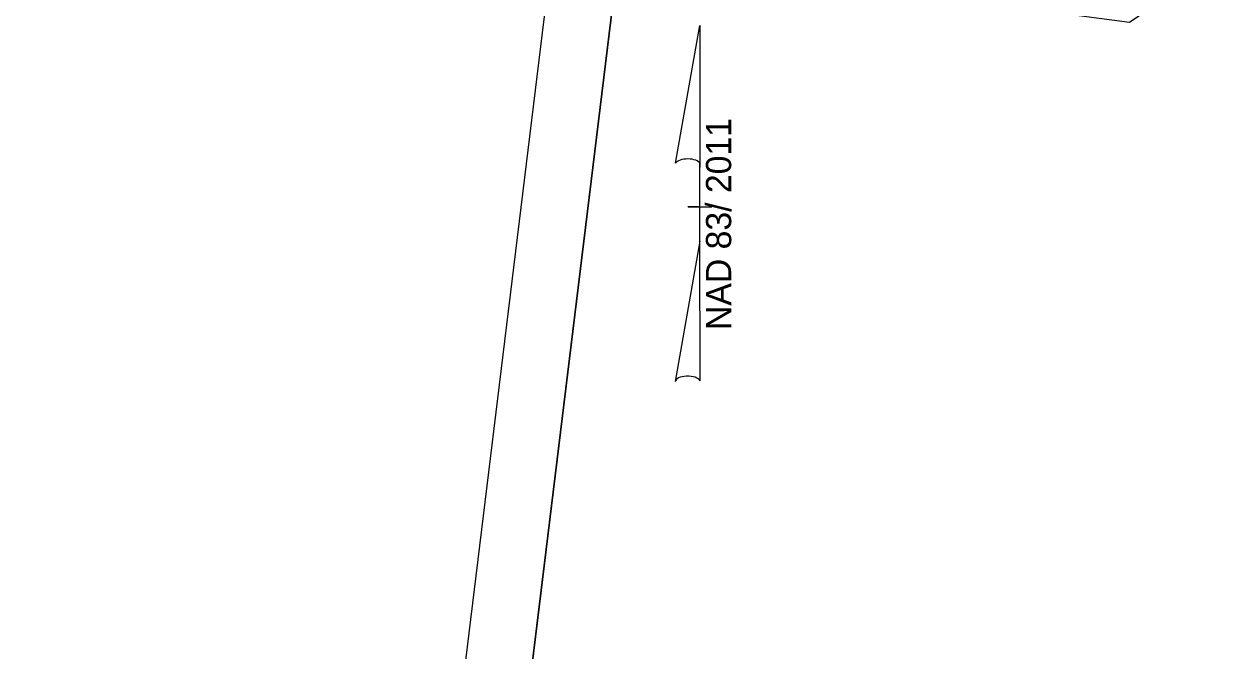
# Model space of a CAD drawing. Extents: x 480792 to 482083, y 490046 to 491850.
# Drawn here: x 480791.8 to 481196.3, y 491399.2 to 491610.4 of the extents above; entities that cross this region are included whole.
import ezdxf

# ---------------------------------------------------------------- set-up
doc = ezdxf.new("R2010")
doc.units = 0
for name, color, linetype in [('Prop North Arrow NAD83 for Plan Sheets CELL', 7, 'Continuous'), ('Sheet Clip Boundary CELL', 7, 'Continuous'), ('Sheet Plan CELL', 7, 'Continuous'), ('Sheet Plot Border Outside CELL', 7, 'Continuous')]:
    doc.layers.add(name, color=color, linetype=linetype)

msp = doc.modelspace()

# ---------------------------------------------------------------- linework, layer by layer
at = {"layer": 'Prop North Arrow NAD83 for Plan Sheets CELL'}
for p, q in [((481011.23, 491563.5), (481019.43, 491609.85)), ((481019.48, 491609.85), (481019.43, 491609.85)), ((481019.48, 491609.85), (481019.43, 491609.85)), ((481019.48, 491609.85), (481019.48, 491562.05)), ((481019.48, 491537.25), (481019.48, 491563.45)), ((481019.48, 491562.05), (481019.48, 491563.4)), ((481015.48, 491548.85), (481015.43, 491548.85)), ((481019.03, 491548.85), (481015.48, 491548.85)), ((481015.53, 491548.85), (481023.53, 491548.85)), ((481019.48, 491537.25), (481011.13, 491490)), ((481019.53, 491490.2), (481019.48, 491537.25))]:
    msp.add_line(p, q, dxfattribs=at)
for centre, start_param, end_param in [((481015.37, 491563), 0.216388, 2.908219), ((481015.37, 491489.83), 0.201328, 3.141593)]:
    msp.add_ellipse(centre, major_axis=(4.23, -0.03), ratio=0.461098, start_param=start_param, end_param=end_param, dxfattribs=at)
at = {"layer": 'Sheet Clip Boundary CELL'}
msp.add_lwpolyline([(480960.89, 490427.66), (481123.7, 490407.77), (481546.78, 490356.1), (481674.49, 490340.53), (481662.51, 490242.06), (481694.92, 490236.5), (481876.58, 490214.31), (482038.38, 491533.84), (481958.33, 491543.66), (481978.88, 491711.23), (481782.84, 491735.27), (481563.21, 491713.66), (481210.33, 491642.39), (481164.2, 491610.96), (481026.3, 491629.16), (480991.92, 491631.99), (480846.54, 490441.62)], close=True, dxfattribs=at)
at = {"layer": 'Sheet Plan CELL'}
for points in [[(481016.19, 491830.58), (480834.33, 490341.61), (481876.58, 490214.31), (482058.44, 491703.26)], [(481876.58, 490214.31), (480834.35, 490341.58), (480991.92, 491631.99), (481140.87, 491613.81), (481165.14, 491812.37), (482058.44, 491703.26)]]:
    msp.add_lwpolyline(points, close=True, dxfattribs=at)
at = {"layer": 'Sheet Plot Border Outside CELL'}
msp.add_lwpolyline([(481878.74, 490046.32), (482082.84, 491717.41), (480995.92, 491850.16), (480791.82, 490179.08)], close=True, dxfattribs=at)

# ---------------------------------------------------------------- texts
at = {"layer": 'Prop North Arrow NAD83 for Plan Sheets CELL'}
msp.add_text('NAD 83/ 2011', height=8.5, rotation=90, dxfattribs=at).set_placement((481030, 491507.33))

doc.saveas('drawing.dxf')
